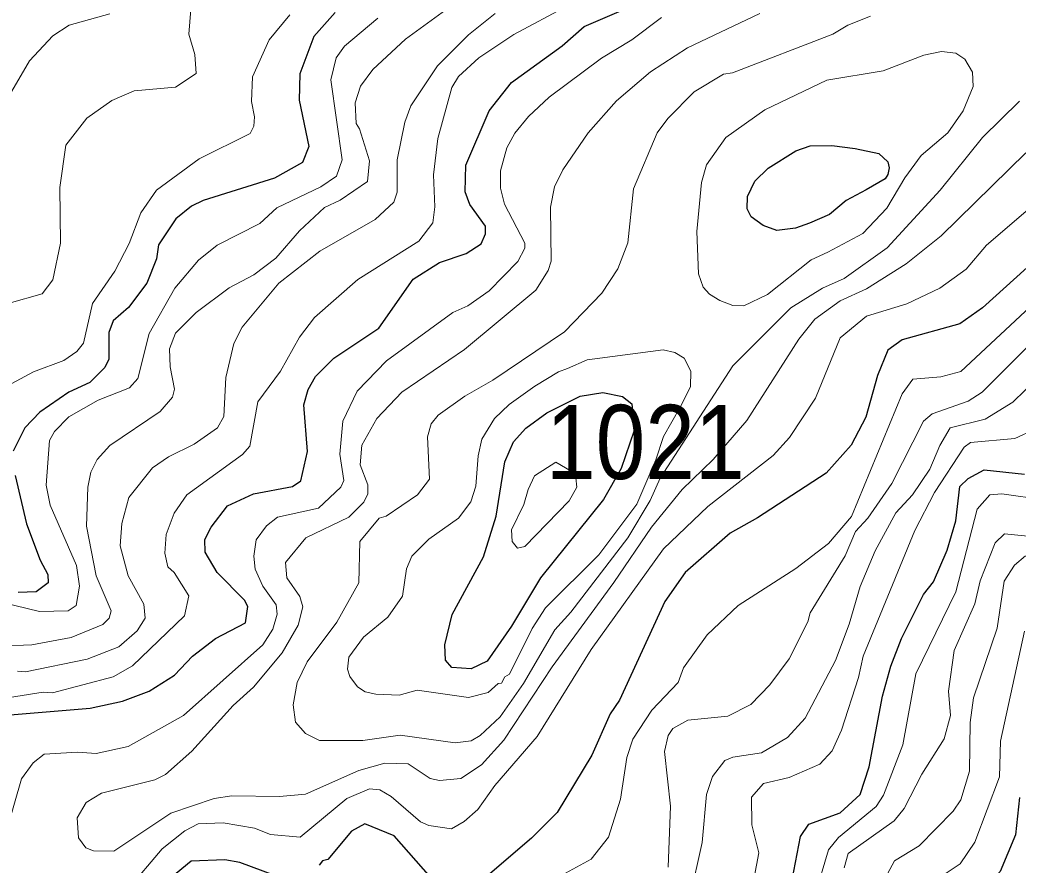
# Model space of a CAD drawing. Extents: x 673.3 to 698.5, y 6984.3 to 7012.3.
# Drawn here: x 682.907 to 683.984, y 6995.709 to 6996.621 of the extents above; entities that cross this region are included whole.
import ezdxf

# ---------------------------------------------------------------- set-up
doc = ezdxf.new("R2010")
doc.units = 0
doc.header["$LTSCALE"] = 0.032
doc.layers.add('1', color=7, linetype='Continuous', lineweight=25)
doc.layers.add('2', color=7, linetype='Continuous', lineweight=13)
doc.layers.add('21', color=7, linetype='Continuous')

msp = doc.modelspace()

# ---------------------------------------------------------------- linework, layer by layer
at = {"layer": '1'}
for points in [[(682.8965, 6995.871), (682.9829, 6995.8783), (683.0176, 6995.8858), (683.0466, 6995.8965), (683.0737, 6995.914), (683.0933, 6995.9343), (683.1182, 6995.9534), (683.1503, 6995.9705), (683.1528, 6995.9882), (683.1493, 6995.9948), (683.1198, 6996.0247), (683.1068, 6996.0465), (683.1066, 6996.0604), (683.1135, 6996.0735), (683.131, 6996.0965), (683.1592, 6996.1095), (683.2012, 6996.1175), (683.21, 6996.1237), (683.2172, 6996.1554), (683.2133, 6996.2057), (683.2182, 6996.2223), (683.2261, 6996.2364), (683.2458, 6996.2561), (683.2942, 6996.2884), (683.3315, 6996.3411), (683.3599, 6996.3593), (683.3886, 6996.3688), (683.4046, 6996.3794), (683.4093, 6996.3903), (683.4094, 6996.3984), (683.3926, 6996.4219), (683.3875, 6996.4354), (683.3882, 6996.4644), (683.4134, 6996.5231), (683.4375, 6996.5536), (683.492, 6996.5929), (683.5159, 6996.6141), (683.5736, 6996.6388)], [(683.2471, 6996.629), (683.2242, 6996.6033), (683.2092, 6996.5627), (683.2085, 6996.5344), (683.2189, 6996.4846), (683.212, 6996.467), (683.1817, 6996.4502), (683.1047, 6996.4263), (683.0921, 6996.4201), (683.0752, 6996.4064), (683.0565, 6996.3784), (683.0543, 6996.3632), (683.0439, 6996.337), (683.0241, 6996.3107), (683.0078, 6996.2963), (683.0031, 6996.2836), (683.0031, 6996.255), (682.9988, 6996.246), (682.9824, 6996.2298), (682.9599, 6996.2195), (682.9284, 6996.1977), (682.9125, 6996.181), (682.8998, 6996.1555)], [(684.005, 6996.3641), (683.9456, 6996.3103)], [(683.9456, 6996.3103), (683.9212, 6996.293), (683.8591, 6996.2757), (683.8435, 6996.2647), (683.8323, 6996.2373), (683.8198, 6996.1924), (683.8038, 6996.162), (683.7769, 6996.132), (683.7029, 6996.0837), (683.6733, 6996.0672), (683.625, 6996.0247), (683.6029, 6995.9934), (683.5538, 6995.8868), (683.544, 6995.8721), (683.5242, 6995.8276), (683.4866, 6995.7657), (683.4589, 6995.738), (683.4089, 6995.6953)], [(683.7402, 6995.6929), (683.7491, 6995.7399), (683.7584, 6995.7531), (683.7922, 6995.7654), (683.8135, 6995.785), (683.8232, 6995.8151), (683.8378, 6995.8913), (683.8467, 6995.9236), (683.8584, 6995.9535), (683.882, 6996.0008), (683.8926, 6996.0146), (683.9076, 6996.0487), (683.9168, 6996.0803), (683.9213, 6996.1174), (683.9301, 6996.1261), (683.9475, 6996.1355), (683.9909, 6996.1309)], [(682.9021, 6996.1294), (682.9143, 6996.0773), (682.9288, 6996.0382), (682.9371, 6996.0224), (682.9376, 6996.0135), (682.9245, 6996.0037), (682.9053, 6996.003)], [(683.9855, 6995.782), (683.9811, 6995.7415), (683.9646, 6995.7022), (683.9323, 6995.6658), (683.9119, 6995.5861), (683.9023, 6995.5675), (683.8673, 6995.517), (683.8251, 6995.4697), (683.7354, 6995.39), (683.6931, 6995.3389), (683.651, 6995.2636), (683.6284, 6995.2053), (683.61, 6995.1668), (683.5839, 6995.1278), (683.5644, 6995.113), (683.5479, 6995.1064)], [(683.3503, 6995.6955), (683.3108, 6995.7407), (683.2792, 6995.7536), (683.2648, 6995.7457), (683.2393, 6995.7149), (683.2336, 6995.7137), (683.2301, 6995.7089)], [(683.1822, 6995.6976), (683.1443, 6995.7116), (683.128, 6995.7146), (683.0917, 6995.7132), (683.0697, 6995.6947)]]:
    msp.add_lwpolyline(points, dxfattribs=at)
for points in [[(683.7143, 6996.4611), (683.7444, 6996.4798), (683.7597, 6996.485), (683.7832, 6996.4856), (683.8082, 6996.4824), (683.8337, 6996.4769), (683.8435, 6996.468), (683.845, 6996.4614), (683.8434, 6996.4544), (683.8407, 6996.4494), (683.8201, 6996.4375), (683.7987, 6996.426), (683.7807, 6996.4111), (683.759, 6996.4018), (683.7438, 6996.3963), (683.7239, 6996.3939), (683.7091, 6996.3992), (683.6961, 6996.4086), (683.6918, 6996.4173), (683.6921, 6996.4304), (683.7001, 6996.4469)], [(683.3734, 6995.9795), (683.4071, 6996.0415), (683.4209, 6996.0855), (683.4303, 6996.1442), (683.4395, 6996.1659), (683.4529, 6996.1806), (683.4756, 6996.1971), (683.5115, 6996.215), (683.536, 6996.219), (683.5572, 6996.2148), (683.5672, 6996.2069), (683.5697, 6996.178), (683.5557, 6996.1369), (683.5367, 6996.1034), (683.4686, 6996.019), (683.4375, 6995.9669), (683.4111, 6995.9291), (683.3939, 6995.9207), (683.373, 6995.9223), (683.3664, 6995.9302), (683.3654, 6995.9465)]]:
    msp.add_lwpolyline(points, close=True, dxfattribs=at)
at = {"layer": '2'}
for points in [[(683.0927, 6996.6458), (683.0894, 6996.6058), (683.0959, 6996.5836), (683.0973, 6996.5631), (683.0749, 6996.5486), (683.0302, 6996.5444), (683.0062, 6996.5341), (682.9792, 6996.5149), (682.9567, 6996.4857), (682.9501, 6996.4402), (682.9509, 6996.3801), (682.9426, 6996.3407), (682.9311, 6996.3254), (682.8596, 6996.3053), (682.847, 6996.2973), (682.8248, 6996.2757), (682.8103, 6996.251), (682.8043, 6996.197), (682.8084, 6996.1566), (682.8068, 6996.1457)], [(682.884, 6995.9451), (682.9199, 6995.9466), (682.9624, 6995.9544), (682.9964, 6995.9686), (683.0033, 6995.9756), (683.0054, 6995.9833), (682.9894, 6996.021), (682.979, 6996.0748), (682.9803, 6996.1167), (682.9837, 6996.133), (682.9904, 6996.1467), (683.0039, 6996.1617), (683.0584, 6996.1983), (683.0716, 6996.214), (683.0739, 6996.2226), (683.069, 6996.2465), (683.0683, 6996.266), (683.0749, 6996.2831), (683.0972, 6996.3054), (683.1327, 6996.3319), (683.1594, 6996.346), (683.183, 6996.3639), (683.2088, 6996.3934), (683.2356, 6996.4186), (683.2525, 6996.4265), (683.2822, 6996.4468), (683.2841, 6996.469), (683.2735, 6996.5036), (683.2698, 6996.5091), (683.2686, 6996.5317), (683.2745, 6996.5497), (683.2877, 6996.5677), (683.3229, 6996.6004), (683.3786, 6996.6405)], [(683.498, 6996.6364), (683.4398, 6996.6052), (683.4023, 6996.5803), (683.3803, 6996.5601), (683.3729, 6996.548), (683.3579, 6996.493), (683.3534, 6996.4537), (683.3549, 6996.4195), (683.3525, 6996.4022), (683.3373, 6996.3822), (683.2716, 6996.341), (683.2249, 6996.2999), (683.2086, 6996.2788), (683.1881, 6996.2419), (683.1639, 6996.2088), (683.1551, 6996.1609), (683.1472, 6996.152), (683.087, 6996.1086), (683.0733, 6996.0887), (683.0649, 6996.0656), (683.0634, 6996.0455), (683.0667, 6996.0307), (683.0733, 6996.0247), (683.0892, 6995.9996), (683.0848, 6995.9781), (683.0285, 6995.9241), (683.0077, 6995.912), (682.9423, 6995.8947), (682.9322, 6995.8954), (682.866, 6995.885)], [(683.2931, 6996.6231), (683.2573, 6996.5926), (683.2482, 6996.5801), (683.2425, 6996.5565), (683.2547, 6996.4699), (683.2488, 6996.4524), (683.2316, 6996.441), (683.1841, 6996.4183), (683.1659, 6996.4012), (683.12, 6996.3779), (683.0996, 6996.3616), (683.0743, 6996.3317), (683.0464, 6996.2825), (683.0342, 6996.2341), (683.0252, 6996.2241), (682.9914, 6996.2108), (682.9599, 6996.1926), (682.9443, 6996.177), (682.9388, 6996.1673), (682.9355, 6996.1188), (682.9396, 6996.0975), (682.9682, 6996.0324), (682.9714, 6996.0099), (682.9679, 6995.9892), (682.9591, 6995.9834), (682.9283, 6995.9826), (682.8318, 6996.006)], [(683.004, 6996.6276), (682.9602, 6996.6154), (682.9424, 6996.6037), (682.9174, 6996.5768), (682.8884, 6996.5269)], [(682.8985, 6996.2286), (682.9217, 6996.2411), (682.9545, 6996.2534), (682.9684, 6996.2633), (682.9757, 6996.2722), (682.9853, 6996.3151), (683.0096, 6996.3498), (683.0249, 6996.3798), (683.0374, 6996.4128), (683.0545, 6996.4372), (683.1006, 6996.4711), (683.1554, 6996.4983), (683.1594, 6996.5064), (683.1602, 6996.5163), (683.157, 6996.5329), (683.158, 6996.5598), (683.1761, 6996.5996), (683.1982, 6996.6264)], [(683.4198, 6996.6279), (683.3911, 6996.6051), (683.3575, 6996.5715), (683.329, 6996.5285), (683.3224, 6996.5106), (683.3142, 6996.4702), (683.3141, 6996.4351), (683.3106, 6996.4243), (683.2903, 6996.4056), (683.2308, 6996.3714), (683.1865, 6996.337), (683.1467, 6996.2893), (683.138, 6996.2719), (683.1293, 6996.235), (683.1269, 6996.193), (683.1204, 6996.1807), (683.0951, 6996.1633), (683.0672, 6996.1494), (683.05, 6996.1376), (683.0245, 6996.1058), (683.0169, 6996.0776), (683.0153, 6996.0536), (683.0237, 6996.0211), (683.0406, 6995.9904), (683.0421, 6995.9756), (683.0337, 6995.9618), (683.0139, 6995.9444), (682.9797, 6995.9313), (682.913, 6995.9175), (682.9045, 6995.9182)], [(683.5993, 6996.6237), (683.5674, 6996.5996), (683.5345, 6996.5798), (683.4782, 6996.5376), (683.4558, 6996.5168), (683.4411, 6996.4987), (683.4324, 6996.4829), (683.4257, 6996.4581), (683.4256, 6996.4396), (683.4299, 6996.4221), (683.4518, 6996.38), (683.4518, 6996.3746), (683.4444, 6996.3604), (683.4135, 6996.3288), (683.3902, 6996.3125), (683.3741, 6996.3054), (683.3024, 6996.2533), (683.271, 6996.2204), (683.2556, 6996.1881), (683.2522, 6996.1523), (683.2564, 6996.1241), (683.2532, 6996.1169), (683.2291, 6996.0942), (683.1848, 6996.0843), (683.1731, 6996.0752), (683.1619, 6996.0599), (683.1594, 6996.0424), (683.161, 6996.0283), (683.1693, 6996.0101), (683.1835, 6995.9897), (683.1846, 6995.9796), (683.18, 6995.9636), (683.1692, 6995.9467), (683.0834, 6995.8703), (683.0237, 6995.8369), (682.9895, 6995.8295), (682.9691, 6995.831), (682.9333, 6995.8286), (682.9214, 6995.8194)], [(683.7054, 6996.628), (683.6275, 6996.5908), (683.5873, 6996.565), (683.5509, 6996.5337), (683.5203, 6996.4991), (683.493, 6996.4593), (683.4838, 6996.4408), (683.4794, 6996.4191), (683.4802, 6996.3608), (683.477, 6996.3507), (683.4638, 6996.3293), (683.3868, 6996.2653), (683.3191, 6996.2194), (683.292, 6996.1908), (683.2761, 6996.1623), (683.2742, 6996.1409), (683.2824, 6996.1194), (683.2824, 6996.1097), (683.2783, 6996.1007), (683.2619, 6996.0844), (683.2155, 6996.0622), (683.1937, 6996.0354), (683.1951, 6996.019), (683.2091, 6995.9988), (683.2122, 6995.9875), (683.2073, 6995.9677), (683.1899, 6995.9381), (683.1591, 6995.9008), (683.1372, 6995.8813), (683.0926, 6995.8319), (683.0642, 6995.8067), (683.0525, 6995.8009), (682.9951, 6995.7866), (682.9787, 6995.7765), (682.9687, 6995.76), (682.9701, 6995.7383), (682.9781, 6995.7276), (682.9863, 6995.7244), (683.0083, 6995.7241), (683.0698, 6995.7651), (683.1166, 6995.7807), (683.1356, 6995.7838), (683.1873, 6995.7831), (683.2153, 6995.7854), (683.2728, 6995.8111), (683.3006, 6995.8189), (683.3259, 6995.8181), (683.3498, 6995.8023), (683.3599, 6995.8002), (683.3829, 6995.8024), (683.4051, 6995.8171), (683.4291, 6995.8436), (683.4813, 6995.923), (683.548, 6996.0138), (683.5885, 6996.0736), (683.6217, 6996.1143), (683.6551, 6996.1468), (683.6912, 6996.1887), (683.7476, 6996.2765), (683.7649, 6996.298), (683.792, 6996.3179), (683.8205, 6996.331)], [(683.9856, 6996.5335), (683.9455, 6996.4941), (683.8998, 6996.4373), (683.8426, 6996.3751), (683.7965, 6996.3419), (683.7731, 6996.3314), (683.7389, 6996.3103), (683.6762, 6996.2477), (683.5977, 6996.1266), (683.587, 6996.1023), (683.563, 6996.0621), (683.5016, 6995.982), (683.4842, 6995.9628), (683.4505, 6995.905), (683.4253, 6995.869), (683.4037, 6995.8487), (683.3939, 6995.843), (683.3765, 6995.8408), (683.3172, 6995.849), (683.2769, 6995.8433), (683.2304, 6995.8433), (683.2153, 6995.8511), (683.2043, 6995.8632), (683.2018, 6995.8819), (683.2063, 6995.9061), (683.2169, 6995.9283), (683.2489, 6995.971), (683.2728, 6996.0136), (683.2739, 6996.0581), (683.2946, 6996.0833), (683.3021, 6996.0855), (683.3359, 6996.1086), (683.3491, 6996.1254), (683.3467, 6996.1711), (683.3509, 6996.1852), (683.3583, 6996.1944), (683.3871, 6996.215), (683.4174, 6996.2324), (683.4947, 6996.2845), (683.5348, 6996.3262), (683.5521, 6996.3526), (683.563, 6996.3806), (683.5691, 6996.4389), (683.5945, 6996.4992), (683.6061, 6996.5148), (683.6347, 6996.5435), (683.6662, 6996.5624), (683.676, 6996.5638), (683.7843, 6996.6057), (683.8003, 6996.6153), (683.8248, 6996.6251)], [(683.8205, 6996.331), (683.8633, 6996.3577), (683.9011, 6996.388), (683.9923, 6996.4775)], [(683.0226, 6995.682), (683.0605, 6995.7265), (683.085, 6995.7458), (683.0995, 6995.7534), (683.1263, 6995.7545), (683.1602, 6995.7488), (683.1775, 6995.7421), (683.2096, 6995.7391), (683.2596, 6995.7808), (683.2841, 6995.7911), (683.2955, 6995.7902), (683.3076, 6995.7828), (683.3392, 6995.7555), (683.3483, 6995.7516), (683.3726, 6995.7481), (683.3863, 6995.7561), (683.4012, 6995.7691), (683.4196, 6995.7948), (683.4652, 6995.8477), (683.5233, 6995.9416), (683.6015, 6996.0501), (683.6491, 6996.0959), (683.7197, 6996.1509), (683.7375, 6996.1705), (683.7656, 6996.2128), (683.7922, 6996.278), (683.8205, 6996.3012), (683.8639, 6996.3148), (683.8997, 6996.3317), (683.928, 6996.3521), (683.9499, 6996.3781), (683.995, 6996.4166)], [(683.4879, 6995.6961), (683.5233, 6995.7154), (683.5421, 6995.7391), (683.5551, 6995.78), (683.5618, 6995.8249), (683.5685, 6995.8447), (683.589, 6995.8762), (683.6173, 6995.9059), (683.6231, 6995.9218), (683.6484, 6995.9576), (683.682, 6995.9891), (683.7444, 6996.0291), (683.7793, 6996.056), (683.8044, 6996.085), (683.8591, 6996.2174), (683.8704, 6996.2333), (683.9008, 6996.236), (683.9224, 6996.2416), (684.0454, 6996.3563)], [(683.6065, 6995.7066), (683.6089, 6995.7724), (683.6025, 6995.8316), (683.6065, 6995.8488), (683.6116, 6995.8563), (683.6277, 6995.8653), (683.671, 6995.8697), (683.6956, 6995.8821), (683.7163, 6995.9035), (683.7372, 6995.9315), (683.7573, 6995.9714), (683.7598, 6995.9812), (683.7973, 6996.0426), (683.8086, 6996.0691), (683.8219, 6996.0832), (683.8478, 6996.1208), (683.8819, 6996.1879), (683.8912, 6996.196), (683.9301, 6996.2095), (683.9451, 6996.2194), (684.0016, 6996.2759)], [(684.0049, 6996.2345), (683.9783, 6996.2085), (683.9484, 6996.1902), (683.9109, 6996.1809), (683.8996, 6996.1618), (683.8889, 6996.1364), (683.8701, 6996.1087), (683.8523, 6996.089), (683.8297, 6996.048), (683.8136, 6996.0095), (683.8019, 6995.9688), (683.7871, 6995.9299), (683.7543, 6995.8674), (683.7354, 6995.8467), (683.7073, 6995.8302), (683.6762, 6995.8253), (683.6677, 6995.8217), (683.6543, 6995.8045), (683.648, 6995.7853), (683.6431, 6995.7334), (683.6297, 6995.6735)], [(683.6978, 6995.688), (683.7042, 6995.7223), (683.6968, 6995.7523), (683.6963, 6995.7824), (683.7094, 6995.797), (683.7371, 6995.8034), (683.77, 6995.8179), (683.7833, 6995.8321), (683.7935, 6995.8545), (683.8119, 6995.9115), (683.8168, 6995.9346), (683.8726, 6996.0699), (683.8938, 6996.111), (683.9258, 6996.1599), (683.9328, 6996.165), (683.9805, 6996.1692), (684.0025, 6996.1793)], [(684.0121, 6996.1031), (683.9665, 6996.1096), (683.9537, 6996.1087), (683.94, 6996.0929), (683.9168, 6996.0037), (683.8736, 6995.9155), (683.8596, 6995.8386), (683.8389, 6995.7844), (683.8308, 6995.7721), (683.7902, 6995.7387), (683.7794, 6995.7256), (683.7649, 6995.6757)], [(683.7963, 6995.706), (683.8006, 6995.7213), (683.8505, 6995.7567), (683.8612, 6995.7701), (683.8801, 6995.8071), (683.9042, 6995.8451), (683.911, 6995.8703), (683.9088, 6995.8967), (683.9152, 6995.9405), (683.9372, 6995.991), (683.943, 6996.0157), (683.9594, 6996.0567), (683.9695, 6996.0665), (684.0228, 6996.0609)], [(683.6856, 6995.4304), (683.744, 6995.5149), (683.8121, 6995.5963), (683.832, 6995.6484), (683.8357, 6995.6855), (683.8508, 6995.7134), (683.8774, 6995.7298), (683.9141, 6995.7673), (683.9222, 6995.7795), (683.9315, 6995.8102), (683.9323, 6995.863), (683.936, 6995.8893), (683.9615, 6995.9647), (683.969, 6996.0154), (683.9802, 6996.0328), (683.9921, 6996.0428)], [(683.9908, 6995.9614), (683.9649, 6995.8428), (683.9639, 6995.8041), (683.9373, 6995.7337), (683.9214, 6995.7103), (683.9011, 6995.6965)], [(682.9214, 6995.8194), (682.9087, 6995.8021), (682.8943, 6995.7522)]]:
    msp.add_lwpolyline(points, dxfattribs=at)
for points in [[(683.6881, 6996.3125), (683.7136, 6996.3247), (683.7607, 6996.362), (683.7786, 6996.3704), (683.8164, 6996.3904), (683.8424, 6996.418), (683.8617, 6996.4506), (683.8795, 6996.4746), (683.9082, 6996.4993), (683.9248, 6996.5231), (683.9354, 6996.5492), (683.9347, 6996.5648), (683.9264, 6996.5787), (683.917, 6996.5853), (683.9013, 6996.5868), (683.8824, 6996.5829), (683.8385, 6996.5662), (683.7778, 6996.5559), (683.7106, 6996.524), (683.6686, 6996.4941), (683.6479, 6996.4645), (683.6424, 6996.4456), (683.6374, 6996.3926), (683.6392, 6996.3472), (683.6441, 6996.3328), (683.6509, 6996.3251), (683.6621, 6996.3181), (683.6762, 6996.3128)], [(683.3199, 6995.9993), (683.3241, 6996.0288), (683.3299, 6996.0424), (683.3483, 6996.0607), (683.3801, 6996.0835), (683.3936, 6996.1009), (683.3989, 6996.118), (683.4014, 6996.1506), (683.4053, 6996.1686), (683.4192, 6996.191), (683.435, 6996.2061), (683.4628, 6996.2257), (683.4883, 6996.2412), (683.4979, 6996.2449), (683.5191, 6996.2542), (683.601, 6996.2651), (683.6135, 6996.2623), (683.6238, 6996.2559), (683.6309, 6996.242), (683.6306, 6996.2252), (683.6196, 6996.203), (683.6014, 6996.1716), (683.5931, 6996.1462), (683.5725, 6996.0985), (683.5317, 6996.0436), (683.4743, 6995.9866), (683.4598, 6995.9644), (683.4354, 6995.915), (683.4304, 6995.9121), (683.4265, 6995.9054), (683.4231, 6995.905), (683.4122, 6995.8952), (683.3909, 6995.8898), (683.3357, 6995.8979), (683.3162, 6995.8925), (683.2909, 6995.8933), (683.2797, 6995.8961), (683.2712, 6995.9015), (683.263, 6995.9126), (683.2606, 6995.9205), (683.2621, 6995.9335), (683.2777, 6995.9551), (683.304, 6995.9765)], [(683.4996, 6996.1021), (683.5078, 6996.1168), (683.5068, 6996.1267), (683.5081, 6996.1304), (683.4852, 6996.1437), (683.4624, 6996.129), (683.4555, 6996.1143), (683.4506, 6996.0981), (683.4375, 6996.0708), (683.438, 6996.0581), (683.4439, 6996.0511), (683.452, 6996.0528)]]:
    msp.add_lwpolyline(points, close=True, dxfattribs=at)

# ---------------------------------------------------------------- texts
at = {"layer": '21', "width": 0.9}
msp.add_text('1021', height=0.08, dxfattribs=at).set_placement((683.4747, 6996.1256))

doc.saveas('drawing.dxf')
